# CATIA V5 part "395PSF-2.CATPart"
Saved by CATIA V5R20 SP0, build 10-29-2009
Part number: 395PSF-2
Source: Unknown
Property "ARTICLENO": "395PSF-2"
Property "BOMINFO": "395PSF-2"
Property "CODE": "395PSF-2"
Property "D": "33.000"
Property "D1": "43.000"
Property "H": "4.000"
Property "L": "200.500"
Property "L1": "6.000"
Property "L2": "170.000"
Property "L3": "10.000"
Property "L4": "6.000"
Property "LINA": "395PSF-2"
Property "MAXLOAD": "3200 Kg"
Property "MDW": "6400 Kg"
Property "NB": "395PSF-2"
Property "NBSYN": "$CODE."
Property "NN": "395PSF"
Property "NT": "FIAT Lifting Pins"
Property "SUPPLIER": "CF"
Bounding box of the stored display mesh (mm): x 0 to 200.5, y -21.5 to 21.5, z -21.5 to 21.5
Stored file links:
  C:\Users\Utente\Desktop\3D files 395PSF\395PSF-2.CATPart
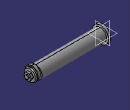
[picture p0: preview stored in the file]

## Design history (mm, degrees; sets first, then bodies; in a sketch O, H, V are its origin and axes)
Body1 "Geometry.1" (main body)
  Solid1 "395PSF-2.catpart": solid without history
